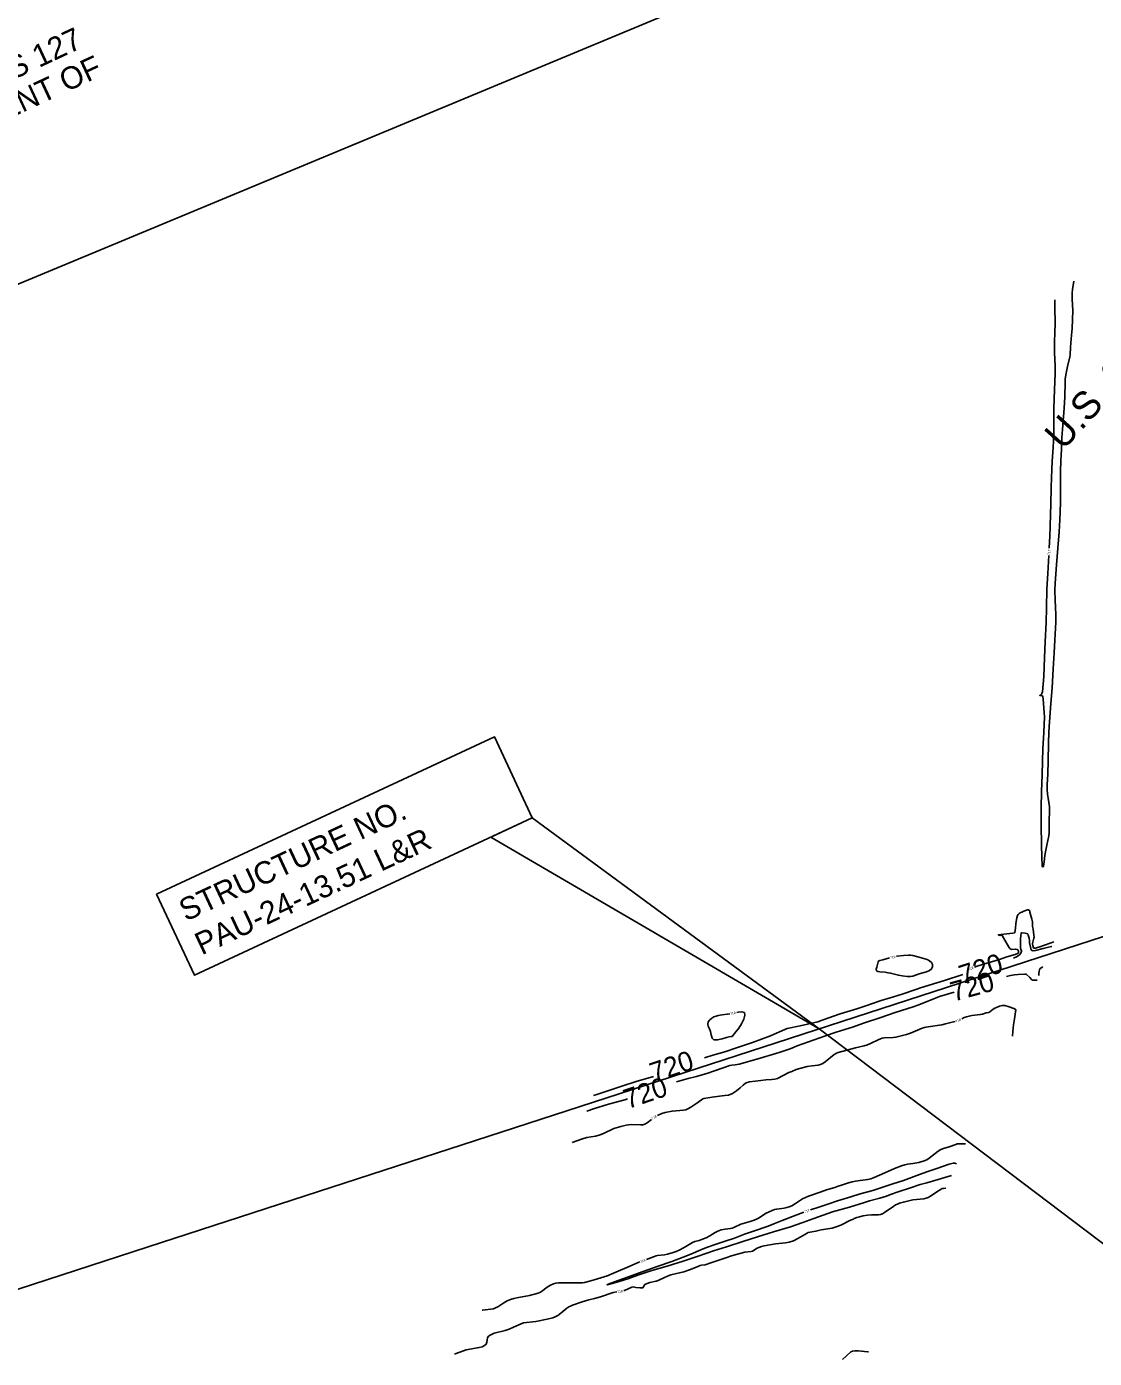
# Model space of a CAD drawing. Extents: x -310467766 to 17062430, y -322263100 to 8322522.
# Drawn here: x 1397865 to 1399656, y 574364 to 576598 of the extents above; entities that cross this region are included whole.
import ezdxf

# ---------------------------------------------------------------- set-up
doc = ezdxf.new("R2010")
doc.units = 0
for name, color, linetype in [('DT_X_Contour_Minor', 7, 'Continuous'), ('Level 14', 7, 'Continuous'), ('Level 19', 7, 'Continuous'), ('Level 40', 7, 'Continuous'), ('SC_Scratch1', 7, 'Continuous')]:
    doc.layers.add(name, color=color, linetype=linetype)

msp = doc.modelspace()

# ---------------------------------------------------------------- linework, layer by layer
at = {"layer": 'DT_X_Contour_Minor'}
for points in [[(1399621.1, 576170.9), (1399618.8, 576156.7), (1399618.4, 576151.3), (1399618.4, 576140.9), (1399619.2, 576121.5), (1399618.9, 576106.3), (1399618.2, 576091.2), (1399617.3, 576080.1), (1399615.5, 576060.2), (1399614.9, 576047.3), (1399614.3, 576043.9), (1399610.6, 576027.7), (1399607.9, 576013.6), (1399606.8, 576006.5), (1399606.6, 576000.8), (1399605.8, 575976.6), (1399605.1, 575958), (1399602.8, 575929.6), (1399601.2, 575908.1), (1399600.2, 575889.3), (1399599.6, 575878.7), (1399599.1, 575870.8), (1399598.7, 575851.2), (1399598.7, 575826.3), (1399598.8, 575799.3), (1399597.4, 575770.7), (1399596.6, 575750.7), (1399594.4, 575723.3), (1399592.2, 575695.2), (1399590, 575664.6), (1399589.5, 575652.1), (1399590, 575636.6), (1399591, 575611.3), (1399590.7, 575599.2), (1399589.3, 575569), (1399588.3, 575547.7), (1399586.5, 575521), (1399584.6, 575489), (1399582.8, 575462.6), (1399580.2, 575431.6), (1399579.1, 575414.4), (1399578.4, 575396.2), (1399577.9, 575366.2), (1399577.3, 575344.4), (1399576.6, 575326.2), (1399576.6, 575318.6), (1399577, 575310.8), (1399577.8, 575303.6), (1399580.2, 575289.1), (1399580.4, 575286), (1399579.7, 575261.8), (1399579.5, 575251.7), (1399579.7, 575249.3), (1399579.6, 575245.9), (1399579, 575240.6), (1399575.8, 575224.9), (1399573.4, 575213.8), (1399572.7, 575207.9), (1399571.5, 575197.3), (1399570.2, 575189.9), (1399569.6, 575188.9), (1399569.1, 575188.8), (1399568.6, 575188.9), (1399568.2, 575189.9), (1399567.9, 575192.6), (1399567.5, 575203.1), (1399567.1, 575227), (1399566.2, 575257), (1399566.4, 575287.5), (1399567.1, 575314.8), (1399568.1, 575343), (1399568.7, 575365.9), (1399569.4, 575386.7), (1399570.8, 575413.7), (1399571.5, 575428), (1399572, 575439.8), (1399571.6, 575447.7), (1399569.5, 575470), (1399569, 575473.8), (1399568.5, 575475.2), (1399567.6, 575475.5), (1399564.7, 575475.9), (1399564, 575476.2), (1399566.1, 575477.4), (1399567.5, 575479.2), (1399568.4, 575482.3), (1399570.8, 575507.6), (1399572.1, 575540), (1399573.2, 575565.9), (1399574.5, 575598.3), (1399575.2, 575622.8), (1399575.9, 575654.4), (1399577.3, 575680.7), (1399579.3, 575710.9)], [(1399580, 575722.9), (1399581.1, 575743.5), (1399581.6, 575758.5), (1399582.1, 575781.4), (1399582.5, 575795), (1399582.9, 575826.1), (1399584.2, 575854.8), (1399585, 575868.7), (1399586.6, 575892), (1399587.5, 575914.3), (1399587.6, 575935.8), (1399587.7, 575958.1), (1399588.7, 575988.5), (1399589.8, 576016.2), (1399589.7, 576028.5), (1399588.5, 576051.1), (1399588.6, 576068.4), (1399589.2, 576085.1), (1399589.6, 576099.1), (1399589, 576127.9), (1399589.4, 576139.4)], [(1399587.8, 575062.7), (1399581.5, 575060.5), (1399562.4, 575054), (1399556.1, 575052.2), (1399554, 575052.1), (1399553.3, 575053.1), (1399552.2, 575057), (1399551.8, 575059.1), (1399551.9, 575060.3), (1399552.8, 575064.4), (1399554.2, 575069.3), (1399554.4, 575071), (1399554.1, 575074), (1399552.7, 575084.2), (1399552, 575088.7), (1399551.8, 575096.3), (1399550.9, 575100.7), (1399547.6, 575112.8), (1399547.2, 575114.7), (1399546.7, 575115.6), (1399545.9, 575116.2), (1399544.8, 575116.6), (1399543.5, 575116.6), (1399540.3, 575115.7), (1399531.3, 575111.8), (1399529.4, 575110.3), (1399527.9, 575108.6), (1399526.8, 575106.9), (1399525.6, 575103.1), (1399524, 575093.6), (1399523.4, 575085.7), (1399522.3, 575078.3), (1399521.4, 575077.9), (1399518.8, 575077.4), (1399504, 575075.5), (1399498.7, 575075.1), (1399495.6, 575074.9), (1399494.7, 575074.7), (1399495, 575074.3), (1399496.1, 575073.9), (1399497.5, 575073.7), (1399498.5, 575073.9), (1399500, 575074.7), (1399500.7, 575073.7), (1399511.8, 575055), (1399514, 575051.9), (1399515.6, 575050.5), (1399516.9, 575050.2), (1399523.4, 575050.7), (1399526.3, 575049.9), (1399527.6, 575048.9), (1399528.3, 575047.5), (1399528.6, 575045.7), (1399528.4, 575044.8), (1399527.9, 575044), (1399526.7, 575043.2), (1399522.5, 575041.6), (1399508.8, 575037.5), (1399496.3, 575033.4), (1399469.6, 575025.5), (1399458.8, 575022), (1399454.6, 575020.5)], [(1399520.1, 575035.7), (1399526.2, 575038.3), (1399530.1, 575041.2), (1399532.1, 575043.8), (1399533.3, 575047.3), (1399533.1, 575048.6), (1399532.3, 575050), (1399531.8, 575053), (1399531.6, 575059.7), (1399531.9, 575068.3), (1399532.6, 575077.5), (1399533.2, 575077.8), (1399534.5, 575077.9), (1399539.3, 575077.2), (1399543.9, 575076.1), (1399544.5, 575074.3), (1399546, 575069), (1399546.8, 575064.4), (1399546.5, 575061), (1399548.9, 575051.6), (1399549.7, 575049.2), (1399550.1, 575048.7), (1399551, 575048.2), (1399552.8, 575048), (1399556.6, 575048.5), (1399569.5, 575051.8), (1399578.9, 575054.2), (1399583.4, 575055), (1399584.4, 575055.3)], [(1399312.2, 575036), (1399301.1, 575032.9), (1399295.7, 575031.7), (1399294.1, 575030.8), (1399293.1, 575029.3), (1399290.5, 575020.6), (1399289.9, 575017.2), (1399290.3, 575014.5), (1399292.5, 575013.1), (1399296, 575012.4), (1399304.8, 575011.8), (1399309.3, 575011.2), (1399313.7, 575010.4), (1399327, 575006.8), (1399333.1, 575006), (1399341.9, 575004.7), (1399346.7, 575004.7), (1399351.4, 575005.6), (1399361.7, 575009), (1399373.8, 575012.4), (1399379, 575014.7), (1399382.5, 575017.6), (1399384.3, 575021.1), (1399384.2, 575024.7), (1399382.2, 575028), (1399379, 575030.9), (1399375.3, 575033.1), (1399371.5, 575034.5), (1399359.5, 575037.5), (1399350.9, 575040), (1399347.2, 575040.6), (1399343.6, 575040.7), (1399335.3, 575040.2), (1399325, 575039), (1399323.9, 575038.7)], [(1399001.7, 574868.1), (1399015.6, 574872.8), (1399035.7, 574878.6), (1399055.6, 574884.9), (1399082.5, 574894.2), (1399112.6, 574905.2), (1399127.6, 574912.2), (1399136.3, 574916), (1399140.6, 574917.3), (1399162.1, 574922), (1399191.6, 574929), (1399199, 574931.4), (1399229.3, 574942.1), (1399257.5, 574950.7), (1399270.7, 574955), (1399298.1, 574964.3), (1399313.2, 574968.8), (1399331.3, 574974.4), (1399356.4, 574983), (1399363.9, 574985.6), (1399391.5, 574994), (1399404.1, 574997.9), (1399435.1, 575008)], [(1399559.4, 574998.8), (1399559, 574998.7), (1399556.7, 574998.5), (1399554.4, 574998.5), (1399552.4, 574998.8), (1399550.9, 574999.3), (1399550, 575000), (1399547.5, 575003.2), (1399541.4, 575008.8), (1399538.8, 575008.9), (1399527.6, 575008.1), (1399521.6, 575007.4), (1399515.1, 575006.4), (1399508.4, 575004.8)], [(1399569.1, 575021), (1399564.5, 575018.2), (1399563.4, 575015.7), (1399562.9, 575013.9), (1399562.5, 575009.8), (1399562.6, 575006.2)], [(1399420.6, 574978.4), (1399396, 574971.2), (1399387.2, 574968.1), (1399361, 574957.4), (1399351.6, 574954.1), (1399321.7, 574944.4), (1399308.6, 574939.7), (1399297.4, 574935.9), (1399268.5, 574926.3), (1399251.7, 574920.6), (1399222.8, 574911.6), (1399204.8, 574905.5), (1399176.4, 574895.4), (1399157.4, 574888.4), (1399152.4, 574886.5), (1399145.2, 574883.6), (1399128.6, 574877.9), (1399121.5, 574875.8), (1399094.9, 574867.6), (1399070.2, 574860.3), (1399059.9, 574857.7), (1399053.4, 574856.8), (1399047.7, 574856.2), (1399044.1, 574855.3), (1399034.7, 574852.1), (1399017.1, 574845.8), (1399007.2, 574842.7), (1398988.1, 574837.3), (1398974.3, 574833.9), (1398955.1, 574828.2)], [(1399055.8, 574944.6), (1399058.3, 574945.1), (1399064.6, 574945.7), (1399068.8, 574944.2), (1399069.6, 574939.7), (1399067.6, 574933.1), (1399063.8, 574925.6), (1399059.2, 574918.3), (1399054.5, 574912), (1399048, 574904), (1399045.7, 574904.1), (1399043.1, 574903.7), (1399038.4, 574902.5), (1399031.4, 574900.3), (1399023.8, 574898.4), (1399017.6, 574898.5), (1399014.4, 574901.6), (1399013.1, 574906.7), (1399012, 574912.4), (1399010.1, 574917.2), (1399008.1, 574921.3), (1399007.1, 574925), (1399008.1, 574928.6), (1399010.7, 574932), (1399014.1, 574934.8), (1399017.7, 574936.9), (1399021.2, 574938.3), (1399024.7, 574939.2), (1399031.6, 574940.3), (1399040, 574941.4), (1399044.1, 574942.2)], [(1399518.2, 574904.8), (1399518.7, 574912.3), (1399519.8, 574923.9), (1399521.4, 574933.9), (1399523.3, 574945.3), (1399523.6, 574948.4), (1399522.8, 574949.9), (1399520.6, 574950.9), (1399512.4, 574953.9), (1399505.2, 574956.1), (1399503, 574956.4), (1399501, 574956.3), (1399496.7, 574955.2), (1399491.3, 574952.9), (1399488.5, 574951.5), (1399485.9, 574949.8), (1399480.4, 574945.3), (1399478.7, 574944.6), (1399474.3, 574943.7), (1399468.1, 574941.7), (1399464.2, 574940.8), (1399455.1, 574939.7), (1399450.3, 574939.2), (1399445.6, 574938.5), (1399441.2, 574937.4), (1399437.2, 574936), (1399433.1, 574933.9)], [(1399422, 574929.4), (1399419.5, 574928.8), (1399405.9, 574925.5), (1399399.5, 574923.5), (1399376.6, 574920.2), (1399373.3, 574920), (1399370.9, 574919.5), (1399367, 574918.2), (1399347.4, 574909.8), (1399340.7, 574907.6), (1399322.8, 574903), (1399318.4, 574902.6), (1399303.6, 574901.9), (1399299.9, 574901.4), (1399296.7, 574900.4), (1399292.8, 574898.6), (1399281.3, 574892.7), (1399275, 574890), (1399269.5, 574888.3), (1399254.8, 574885.3), (1399226, 574877.3), (1399223, 574876), (1399219.5, 574873.7), (1399204.4, 574861.6), (1399200.2, 574858.9), (1399196.5, 574857.2), (1399192.4, 574856.2), (1399182.3, 574855), (1399173.8, 574853.8), (1399161.6, 574850.7), (1399155.5, 574848.6), (1399148.4, 574845.7), (1399143.4, 574843.7), (1399124.2, 574833.7), (1399119.9, 574832.7), (1399114.9, 574832.1), (1399104.6, 574831.5), (1399096.3, 574830.2), (1399087, 574829), (1399077.1, 574828), (1399073.5, 574827.2), (1399070.3, 574825.7), (1399066.5, 574822.7), (1399061.5, 574818), (1399055.4, 574812.8), (1399048.9, 574808.4), (1399042.2, 574805.9), (1399036, 574805), (1399027.1, 574804.2), (1399014.5, 574802.2), (1399000.9, 574800.3), (1398998.8, 574799.4), (1398990.7, 574793.7), (1398978.7, 574785.4), (1398974.1, 574782.8), (1398970.3, 574781.4), (1398966.3, 574780.8), (1398947.3, 574779.2), (1398935.6, 574776.7), (1398930.1, 574775.2), (1398924, 574772.5), (1398923.1, 574771.9)], [(1398815.9, 574805.1), (1398819.6, 574806.4), (1398841.1, 574813.7), (1398863, 574820.7), (1398887.2, 574828.5), (1398916.3, 574837)], [(1398872.9, 574799.6), (1398868.1, 574798), (1398841, 574790.7), (1398815.8, 574782.6), (1398804.4, 574778.9), (1398804.2, 574778.9)], [(1398913.1, 574765.2), (1398905.5, 574759.6), (1398901.5, 574757.2), (1398898.1, 574756.2), (1398894.3, 574756), (1398878.9, 574756.5), (1398874.5, 574756.2), (1398870.6, 574755.5), (1398861.7, 574753.2), (1398849.7, 574749.6), (1398832.6, 574741.4), (1398825.3, 574738.7), (1398818.9, 574737), (1398804.4, 574734.7), (1398795.3, 574731.8), (1398780, 574726.2)], [(1398904.4, 574530.2), (1398920.6, 574536.4), (1398923.1, 574537), (1398934.7, 574538.1), (1398939.9, 574539.2), (1398949.3, 574541.8), (1398954.4, 574543.5), (1398959.5, 574545.8), (1398967.5, 574550.1), (1398981.6, 574558.8), (1398985.3, 574560.3), (1398993, 574562.3), (1398998.6, 574564.2), (1399004.8, 574566.7), (1399010.6, 574569.6), (1399019.5, 574575.5), (1399024.2, 574577.9), (1399030, 574579.7), (1399036.2, 574580.9), (1399045.3, 574582.2), (1399048.1, 574582.8), (1399051, 574583.9), (1399062.8, 574589.4), (1399066.4, 574590.6), (1399078.3, 574593.7), (1399083.2, 574595.5), (1399087.9, 574597.5), (1399092.2, 574599.7), (1399105.3, 574607.7), (1399110.3, 574610.4), (1399115, 574612.5), (1399119.2, 574613.9), (1399123, 574614.7), (1399135.1, 574616.2), (1399139.6, 574617.2), (1399144, 574618.5), (1399148.4, 574620.4), (1399152.7, 574622.8), (1399166, 574631.9), (1399171, 574634.4), (1399176.3, 574636.6), (1399195.6, 574643.1), (1399206.4, 574646.8), (1399220.4, 574651), (1399226.1, 574653.1), (1399231.6, 574654.7), (1399243.2, 574658.8), (1399249.5, 574660.6), (1399255, 574661.8), (1399275.2, 574664.2), (1399280.8, 574665.7), (1399286.5, 574667.7), (1399304.3, 574675.6), (1399320.2, 574682.6), (1399332.4, 574687.3), (1399337.8, 574688.9), (1399342.4, 574689.8), (1399351, 574691), (1399361.1, 574693.1), (1399370.4, 574695.8), (1399374.5, 574697.5), (1399378.8, 574700.1), (1399393.4, 574711.8), (1399397.9, 574714.5), (1399402.3, 574716.4), (1399412.1, 574719.4), (1399423.4, 574722.8), (1399425.4, 574724), (1399426.6, 574724.1), (1399434.8, 574724.3), (1399439.2, 574724.2)], [(1399168.5, 574609.4), (1399156.5, 574605), (1399131.8, 574595.5), (1399118.2, 574589.8), (1399108.3, 574586), (1399083.9, 574577.8), (1399068.8, 574572.4), (1399052.1, 574566.1), (1399036.3, 574560.9), (1399021.6, 574556.1), (1399005.4, 574550.4), (1398995.4, 574546.5), (1398978.9, 574539.4), (1398966.2, 574534), (1398947.2, 574527), (1398922.2, 574518.5), (1398898.7, 574510), (1398872.5, 574500.4), (1398844.9, 574490.6), (1398840.1, 574488.7), (1398838.4, 574487.8), (1398840.7, 574488.1), (1398853, 574491.4), (1398873.4, 574497.8), (1398882.4, 574501.1), (1398893.1, 574505.1), (1398908.6, 574510.3), (1398913.7, 574511.5), (1398939.4, 574519.1), (1398966.1, 574527.4), (1398990.9, 574536), (1399016.7, 574544.5), (1399038.8, 574551.5), (1399066.1, 574560.4), (1399090.9, 574568.3), (1399117.4, 574576.5), (1399145.9, 574585.2), (1399166.6, 574592.3), (1399185, 574598.9), (1399208.4, 574607.5), (1399216.7, 574610), (1399245.2, 574618.2), (1399269.9, 574626), (1399278.3, 574628.4), (1399295.9, 574633), (1399306.8, 574636.3), (1399313.9, 574639), (1399326.8, 574643.4), (1399347.4, 574650.1), (1399363.5, 574655.7), (1399374.8, 574658.8), (1399393.8, 574664.1), (1399416.1, 574671.3)], [(1399424.5, 574690.5), (1399421.5, 574692), (1399418.8, 574692), (1399412.2, 574689.9), (1399391.2, 574682.9), (1399374.8, 574677.4), (1399357.7, 574671.1), (1399335.7, 574662.9), (1399317.8, 574657), (1399294, 574649.2), (1399284.1, 574646), (1399263, 574640.5), (1399246.9, 574635.3), (1399224.6, 574628.6), (1399208.8, 574623.1), (1399193.4, 574618), (1399179.8, 574613.4)], [(1399406.5, 574649.7), (1399402.8, 574649.4), (1399399.9, 574649), (1399398.4, 574648.3), (1399391.4, 574643.5), (1399381, 574636.4), (1399377.1, 574634.1), (1399373.6, 574632.9), (1399369.7, 574632.2), (1399351.4, 574630.3), (1399335.3, 574626.5), (1399330.9, 574625.3), (1399328.5, 574624.4), (1399325.7, 574622.7), (1399323.9, 574622.4), (1399322.2, 574621.6), (1399319.1, 574619.6), (1399303.8, 574608.8), (1399300.1, 574606.6), (1399297, 574605.6), (1399293.4, 574605.2), (1399282, 574604.9), (1399275.1, 574604.3), (1399268.1, 574603.2), (1399261.8, 574601.8), (1399257, 574600.5), (1399252.7, 574598.7), (1399251.4, 574597.8), (1399246.8, 574596.4), (1399230.4, 574588), (1399222.8, 574584.8), (1399215.7, 574582.9), (1399197.6, 574579.7), (1399188.5, 574577.7), (1399175.8, 574575.2), (1399173.8, 574574.3), (1399158.3, 574565.2), (1399150.8, 574561.7), (1399143.8, 574559.5), (1399137.5, 574558.4), (1399120.9, 574556.2), (1399101.8, 574553.3), (1399097.4, 574552.2), (1399092.7, 574550.5), (1399090.1, 574549.2), (1399082.4, 574544.1), (1399079.9, 574543.4), (1399069.2, 574542.3), (1399057, 574539.3), (1399047.1, 574536.4), (1399037.4, 574533.1), (1399024.4, 574528.3), (1399012.6, 574524.7), (1399003.1, 574521), (1398996.8, 574520.7), (1398994.3, 574520), (1398986.6, 574516.9), (1398976.9, 574513.1), (1398967, 574509.7), (1398945.6, 574504.3), (1398939.7, 574502.3), (1398934.5, 574500.2), (1398924.1, 574494.8), (1398920.5, 574493.7), (1398910, 574491.4), (1398902.8, 574489.1), (1398901.8, 574488.2), (1398899.9, 574485.2), (1398898.5, 574482.9), (1398897.6, 574482.6), (1398893.2, 574482.8), (1398886.7, 574483.5), (1398882.1, 574484.1), (1398879.7, 574483.6), (1398867.9, 574478.4), (1398866.5, 574478)], [(1398629.2, 574445.1), (1398629.7, 574445.2), (1398648.2, 574447.6), (1398651.4, 574448.9), (1398655.1, 574451), (1398665.4, 574457.5), (1398671.1, 574460.6), (1398676.7, 574463), (1398681.9, 574464.7), (1398686.9, 574465.9), (1398708.5, 574470), (1398723.1, 574473.6), (1398725.5, 574474.7), (1398728.5, 574476.7), (1398738.2, 574484), (1398743.6, 574487.4), (1398748.4, 574489.5), (1398752.7, 574490.6), (1398757, 574491.1), (1398767.1, 574491.3), (1398797.3, 574490.9), (1398800.3, 574491.4), (1398811.1, 574494.5), (1398833.7, 574501.1), (1398834.8, 574501.4), (1398837.3, 574502.2), (1398853, 574508.7), (1398875.3, 574518.2), (1398890.5, 574525), (1398893.1, 574526)], [(1398854.7, 574475.7), (1398848.6, 574474.7), (1398827.5, 574467.5), (1398817.5, 574464.9), (1398808, 574462.6), (1398796.9, 574459.3), (1398780.5, 574453.5), (1398777.2, 574452.2), (1398774.4, 574450.7), (1398771.1, 574448.3), (1398761, 574440.3), (1398755.8, 574436.5), (1398751.3, 574434), (1398747.2, 574432.5), (1398737.8, 574430.4), (1398718.8, 574426.4), (1398698.5, 574424.1), (1398681.6, 574416.5), (1398674, 574413.5), (1398667.4, 574411.3), (1398649.1, 574406.4), (1398645.5, 574405), (1398642.3, 574403.4), (1398639.8, 574401.4), (1398638.1, 574398.7), (1398637.4, 574395.2), (1398637, 574391.5), (1398635.8, 574388.2), (1398633.1, 574385.7), (1398629, 574384), (1398623.9, 574382.7), (1398602.2, 574378.7), (1398585.1, 574372.3), (1398582.8, 574371.4)], [(1399233.1, 574362.5), (1399247.2, 574375.1), (1399250, 574376.5), (1399253.6, 574377), (1399259.2, 574376.8), (1399275.9, 574375.4), (1399276.6, 574375.4)]]:
    msp.add_lwpolyline(points, dxfattribs=at)
at = {"layer": 'Level 14'}
msp.add_lwpolyline([(1396045.7, 573892.7), (1398068.9, 574551.5), (1399780.9, 575107.6), (1401168.4, 575558.4)], dxfattribs=at)
at = {"layer": 'Level 40'}
msp.add_line((1399194.3, 574917.1), (1399714.5, 574523.1), dxfattribs=at)
for points in [[(1398083, 575142.7), (1398649.4, 575406.9), (1398712.8, 575270.9), (1398146.4, 575006.8)], [(1398643.3, 575238.5), (1399194.3, 574917.1), (1398712.8, 575270.9)]]:
    msp.add_lwpolyline(points, close=True, dxfattribs=at)
at = {"layer": 'SC_Scratch1'}
msp.add_lwpolyline([(1392212.4, 573822.1), (1393676.3, 570715.4), (1396857.5, 571041.4), (1399761.2, 572912.7), (1399601.4, 573251.9), (1400998.4, 575913.7), (1400551.7, 577289.3)], close=True, dxfattribs=at)

# ---------------------------------------------------------------- texts
at = {"layer": 'Level 19'}
for s, height, rotation, p in [('717', 4, 86.7974, (1399581.3, 575711.6)), ('718', 4, 13.1035, (1399313.4, 575034.2)), ('720', 33, 18.2315, (1399435.1, 574990.2)), ('720', 33, 15.4813, (1399419.4, 574962.4)), ('718', 4, 18.8274, (1399444.6, 575015)), ('718', 4, 10.9206, (1399045.2, 574940.4)), ('718', 4, 21.6521, (1399423.6, 574927.4)), ('720', 33, 18.6154, (1398916.8, 574826.8)), ('720', 33, 18.6727, (1398872.8, 574782.2)), ('718', 4, 32.3091, (1398914.6, 574764.2)), ('717', 4, 19.9447, (1399169.9, 574607.8)), ('718', 4, 19.9619, (1398894.5, 574524.4)), ('718', 4, 9.5569, (1398855.8, 574473.9))]:
    msp.add_text(s, height=height, rotation=rotation, dxfattribs=at).set_placement(p)
at = {"layer": 'Level 40'}
for s, height, rotation, p in [('THE PROJECT ALSO INCLUDES AREAS OF FULL DEPTH PAVEMENT REPLACEMENT TO', 37.5, 25, (1396020.4, 575844.6)), ('3" ASPHALT OVERLAY AND TO MAINTAIN VERTICAL CLEARANCE UNDER THE US 127', 37.5, 25, (1396091.7, 575691.7)), ('OVERHEAD BRIDGE. INCIDENTAL WORK INCLUDES RE-GRADING, REPLACEMENT OF', 37.5, 25, (1396115.5, 575640.7)), ('U.S. 24', 46.8, 47.8113, (1399603, 575885.5)), ('STRUCTURE NO.', 37.5, 25, (1398132, 575096.6)), ('PAU-24-13.51 L&R', 37.5, 25, (1398158.5, 575040))]:
    msp.add_text(s, height=height, rotation=rotation, dxfattribs=at).set_placement(p)

doc.saveas('drawing.dxf')
